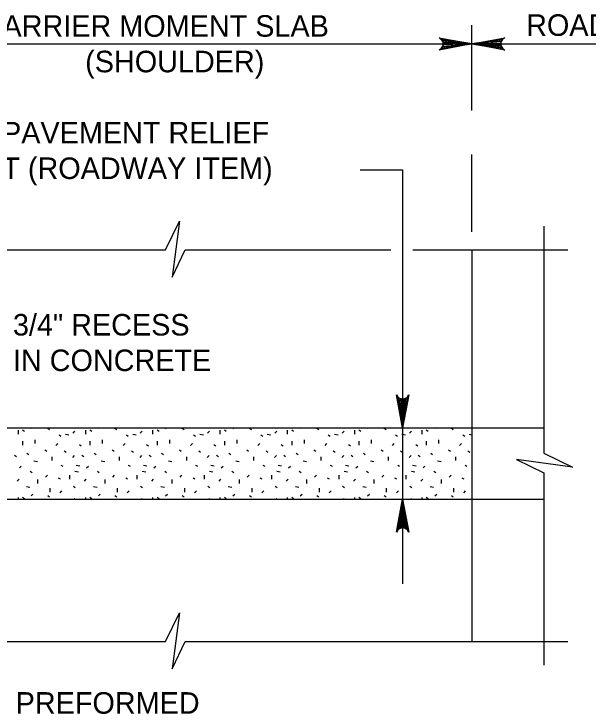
# Model space of a CAD drawing. Extents: x 638167 to 640248, y 296544 to 298920.
# Drawn here: x 640003.4 to 640085.5, y 296853.3 to 296953.1 of the extents above; entities that cross this region are included whole.
import ezdxf

# ---------------------------------------------------------------- set-up
doc = ezdxf.new("R2010")
doc.units = 0
doc.layers.add('1', color=7, linetype='Continuous')

msp = doc.modelspace()

# ---------------------------------------------------------------- linework, layer by layer
at = {"layer": '1'}
for p, q in [((640068.761, 296939.399), (640068.761, 296951.547)), ((639941.261, 296948.882), (640107.801, 296948.882)), ((640068.761, 296922.077), (640068.761, 296933.1)), ((640052.814, 296930.906), (640058.871, 296930.906)), ((640058.871, 296930.906), (640058.871, 296871.848)), ((640079.03, 296922.878), (640079.03, 296890.471)), ((639980.08, 296919.492), (640025.054, 296919.492)), ((640027.825, 296919.492), (640057.194, 296919.492)), ((640060.344, 296919.492), (640082.417, 296919.492)), ((640068.761, 296919.492), (640068.761, 296863.612)), ((639987.481, 296894.092), (640079.03, 296894.092)), ((640004.053, 296893.218), (640004.053, 296893.76)), ((640004.912, 296893.58), (640004.641, 296893.76)), ((640005.861, 296893.987), (640005.966, 296894.092)), ((640008.499, 296893.806), (640008.228, 296893.986)), ((640013.653, 296893.218), (640013.653, 296893.76)), ((640014.512, 296893.58), (640014.241, 296893.76)), ((640015.461, 296893.987), (640015.566, 296894.092)), ((640018.099, 296893.806), (640017.828, 296893.986)), ((640023.253, 296893.218), (640023.253, 296893.76)), ((640024.112, 296893.58), (640023.841, 296893.76)), ((640025.061, 296893.987), (640025.166, 296894.092)), ((640027.699, 296893.806), (640027.428, 296893.986)), ((640032.853, 296893.218), (640032.853, 296893.76)), ((640033.712, 296893.58), (640033.441, 296893.76)), ((640034.661, 296893.987), (640034.766, 296894.092)), ((640037.299, 296893.806), (640037.028, 296893.986)), ((640042.453, 296893.218), (640042.453, 296893.76)), ((640043.312, 296893.58), (640043.041, 296893.76)), ((640044.261, 296893.987), (640044.366, 296894.092)), ((640046.899, 296893.806), (640046.628, 296893.986)), ((640052.053, 296893.218), (640052.053, 296893.76)), ((640052.912, 296893.58), (640052.641, 296893.76)), ((640053.861, 296893.987), (640053.966, 296894.092)), ((640056.499, 296893.806), (640056.228, 296893.986)), ((640061.653, 296893.218), (640061.653, 296893.76)), ((640062.512, 296893.58), (640062.241, 296893.76)), ((640063.461, 296893.987), (640063.566, 296894.092)), ((640066.099, 296893.806), (640065.828, 296893.986)), ((640010.127, 296892.856), (640009.855, 296893.037)), ((640010.76, 296893.173), (640011.257, 296893.082)), ((640011.845, 296893.354), (640012.116, 296893.625)), ((640019.727, 296892.856), (640019.455, 296893.037)), ((640020.36, 296893.173), (640020.857, 296893.082)), ((640021.445, 296893.354), (640021.716, 296893.625)), ((640029.327, 296892.856), (640029.055, 296893.037)), ((640029.96, 296893.173), (640030.457, 296893.082)), ((640031.045, 296893.354), (640031.316, 296893.625)), ((640038.927, 296892.856), (640038.655, 296893.037)), ((640039.56, 296893.173), (640040.057, 296893.082)), ((640040.645, 296893.354), (640040.916, 296893.625)), ((640048.527, 296892.856), (640048.255, 296893.037)), ((640049.16, 296893.173), (640049.657, 296893.082)), ((640050.245, 296893.354), (640050.516, 296893.625)), ((640058.127, 296892.856), (640057.855, 296893.037)), ((640058.76, 296893.173), (640059.257, 296893.082)), ((640059.845, 296893.354), (640060.116, 296893.625)), ((640067.727, 296892.856), (640067.455, 296893.037)), ((640068.36, 296893.173), (640068.761, 296893.1)), ((640004.686, 296891.636), (640004.686, 296892.178)), ((640006.449, 296891.862), (640006.449, 296892.404)), ((640009.404, 296891.59), (640009.675, 296891.862)), ((640013.02, 296891.5), (640012.749, 296891.681)), ((640014.286, 296891.636), (640014.286, 296892.178)), ((640016.049, 296891.862), (640016.049, 296892.404)), ((640019.004, 296891.59), (640019.275, 296891.862)), ((640022.62, 296891.5), (640022.349, 296891.681)), ((640023.886, 296891.636), (640023.886, 296892.178)), ((640025.649, 296891.862), (640025.649, 296892.404)), ((640028.604, 296891.59), (640028.875, 296891.862)), ((640032.22, 296891.5), (640031.949, 296891.681)), ((640033.486, 296891.636), (640033.486, 296892.178)), ((640035.249, 296891.862), (640035.249, 296892.404)), ((640038.204, 296891.59), (640038.475, 296891.862)), ((640041.82, 296891.5), (640041.549, 296891.681)), ((640043.086, 296891.636), (640043.086, 296892.178)), ((640044.849, 296891.862), (640044.849, 296892.404)), ((640047.804, 296891.59), (640048.075, 296891.862)), ((640051.42, 296891.5), (640051.149, 296891.681)), ((640052.686, 296891.636), (640052.686, 296892.178)), ((640054.449, 296891.862), (640054.449, 296892.404)), ((640057.404, 296891.59), (640057.675, 296891.862)), ((640061.02, 296891.5), (640060.749, 296891.681)), ((640062.286, 296891.636), (640062.286, 296892.178)), ((640064.049, 296891.862), (640064.049, 296892.404)), ((640067.004, 296891.59), (640067.275, 296891.862)), ((640008.093, 296890.732), (640007.821, 296890.912)), ((640010.85, 296890.596), (640010.579, 296890.777)), ((640017.693, 296890.732), (640017.421, 296890.912)), ((640020.45, 296890.596), (640020.179, 296890.777)), ((640027.293, 296890.732), (640027.021, 296890.912)), ((640030.05, 296890.596), (640029.779, 296890.777)), ((640036.893, 296890.732), (640036.621, 296890.912)), ((640039.65, 296890.596), (640039.379, 296890.777)), ((640046.493, 296890.732), (640046.221, 296890.912)), ((640049.25, 296890.596), (640048.979, 296890.777)), ((640056.093, 296890.732), (640055.821, 296890.912)), ((640058.85, 296890.596), (640058.579, 296890.777)), ((640065.693, 296890.732), (640065.421, 296890.912)), ((640068.45, 296890.596), (640068.179, 296890.777)), ((640003.782, 296889.963), (640003.51, 296890.144)), ((640005.545, 296890.234), (640005.273, 296890.415)), ((640008.861, 296889.421), (640008.861, 296889.963)), ((640011.8, 296889.873), (640012.071, 296890.144)), ((640013.382, 296889.963), (640013.11, 296890.144)), ((640015.145, 296890.234), (640014.873, 296890.415)), ((640018.461, 296889.421), (640018.461, 296889.963)), ((640021.4, 296889.873), (640021.671, 296890.144)), ((640022.982, 296889.963), (640022.71, 296890.144)), ((640024.745, 296890.234), (640024.473, 296890.415)), ((640028.061, 296889.421), (640028.061, 296889.963)), ((640031, 296889.873), (640031.271, 296890.144)), ((640032.582, 296889.963), (640032.31, 296890.144)), ((640034.345, 296890.234), (640034.073, 296890.415)), ((640037.661, 296889.421), (640037.661, 296889.963)), ((640040.6, 296889.873), (640040.871, 296890.144)), ((640042.182, 296889.963), (640041.91, 296890.144)), ((640043.945, 296890.234), (640043.673, 296890.415)), ((640047.261, 296889.421), (640047.261, 296889.963)), ((640050.2, 296889.873), (640050.471, 296890.144)), ((640051.782, 296889.963), (640051.51, 296890.144)), ((640053.545, 296890.234), (640053.273, 296890.415)), ((640056.861, 296889.421), (640056.861, 296889.963)), ((640059.8, 296889.873), (640060.071, 296890.144)), ((640061.382, 296889.963), (640061.11, 296890.144)), ((640063.145, 296890.234), (640062.873, 296890.415)), ((640066.461, 296889.421), (640066.461, 296889.963)), ((640006.268, 296889.375), (640006.765, 296889.285)), ((640010.443, 296888.562), (640010.172, 296888.742)), ((640012.297, 296888.788), (640012.794, 296888.697)), ((640015.868, 296889.375), (640016.365, 296889.285)), ((640020.043, 296888.562), (640019.772, 296888.742)), ((640021.897, 296888.788), (640022.394, 296888.697)), ((640025.468, 296889.375), (640025.965, 296889.285)), ((640029.643, 296888.562), (640029.372, 296888.742)), ((640031.497, 296888.788), (640031.994, 296888.697)), ((640035.068, 296889.375), (640035.565, 296889.285)), ((640039.243, 296888.562), (640038.972, 296888.742)), ((640041.097, 296888.788), (640041.594, 296888.697)), ((640044.668, 296889.375), (640045.165, 296889.285)), ((640048.843, 296888.562), (640048.572, 296888.742)), ((640050.697, 296888.788), (640051.194, 296888.697)), ((640054.268, 296889.375), (640054.765, 296889.285)), ((640058.443, 296888.562), (640058.172, 296888.742)), ((640060.297, 296888.788), (640060.794, 296888.697)), ((640063.868, 296889.375), (640064.365, 296889.285)), ((640068.043, 296888.562), (640067.772, 296888.742)), ((640004.189, 296888.381), (640004.46, 296888.652)), ((640005.997, 296887.703), (640005.725, 296887.884)), ((640012.116, 296887.929), (640012.613, 296887.838)), ((640013.789, 296888.381), (640014.06, 296888.652)), ((640015.597, 296887.703), (640015.325, 296887.884)), ((640021.716, 296887.929), (640022.213, 296887.838)), ((640023.389, 296888.381), (640023.66, 296888.652)), ((640025.197, 296887.703), (640024.925, 296887.884)), ((640031.316, 296887.929), (640031.813, 296887.838)), ((640032.989, 296888.381), (640033.26, 296888.652)), ((640034.797, 296887.703), (640034.525, 296887.884)), ((640040.916, 296887.929), (640041.413, 296887.838)), ((640042.589, 296888.381), (640042.86, 296888.652)), ((640044.397, 296887.703), (640044.125, 296887.884)), ((640050.516, 296887.929), (640051.013, 296887.838)), ((640052.189, 296888.381), (640052.46, 296888.652)), ((640053.997, 296887.703), (640053.725, 296887.884)), ((640060.116, 296887.929), (640060.613, 296887.838)), ((640061.789, 296888.381), (640062.06, 296888.652)), ((640063.597, 296887.703), (640063.325, 296887.884)), ((640079.03, 296887.7), (640079.03, 296860.225)), ((640003.872, 296886.482), (640004.143, 296886.753)), ((640006.811, 296886.166), (640006.811, 296886.708)), ((640007.912, 296887.07), (640008.183, 296887.341)), ((640010.037, 296886.753), (640009.765, 296886.934)), ((640011.393, 296886.799), (640011.393, 296887.341)), ((640013.472, 296886.482), (640013.743, 296886.753)), ((640016.411, 296886.166), (640016.411, 296886.708)), ((640017.512, 296887.07), (640017.783, 296887.341)), ((640019.637, 296886.753), (640019.365, 296886.934)), ((640020.993, 296886.799), (640020.993, 296887.341)), ((640023.072, 296886.482), (640023.343, 296886.753)), ((640026.011, 296886.166), (640026.011, 296886.708)), ((640027.112, 296887.07), (640027.383, 296887.341)), ((640029.237, 296886.753), (640028.965, 296886.934)), ((640030.593, 296886.799), (640030.593, 296887.341)), ((640032.672, 296886.482), (640032.943, 296886.753)), ((640035.611, 296886.166), (640035.611, 296886.708)), ((640036.712, 296887.07), (640036.983, 296887.341)), ((640038.837, 296886.753), (640038.565, 296886.934)), ((640040.193, 296886.799), (640040.193, 296887.341)), ((640042.272, 296886.482), (640042.543, 296886.753)), ((640045.211, 296886.166), (640045.211, 296886.708)), ((640046.312, 296887.07), (640046.583, 296887.341)), ((640048.437, 296886.753), (640048.165, 296886.934)), ((640049.793, 296886.799), (640049.793, 296887.341)), ((640051.872, 296886.482), (640052.143, 296886.753)), ((640054.811, 296886.166), (640054.811, 296886.708)), ((640055.912, 296887.07), (640056.183, 296887.341)), ((640058.037, 296886.753), (640057.765, 296886.934)), ((640059.393, 296886.799), (640059.393, 296887.341)), ((640061.472, 296886.482), (640061.743, 296886.753)), ((640064.411, 296886.166), (640064.411, 296886.708)), ((640065.512, 296887.07), (640065.783, 296887.341)), ((640067.637, 296886.753), (640067.365, 296886.934)), ((640005.183, 296885.743), (640005.681, 296885.652)), ((640012.161, 296885.562), (640011.89, 296885.743)), ((640014.783, 296885.743), (640015.281, 296885.652)), ((640021.761, 296885.562), (640021.49, 296885.743)), ((640024.383, 296885.743), (640024.881, 296885.652)), ((640031.361, 296885.562), (640031.09, 296885.743)), ((640033.983, 296885.743), (640034.481, 296885.652)), ((640040.961, 296885.562), (640040.69, 296885.743)), ((640043.583, 296885.743), (640044.081, 296885.652)), ((640050.561, 296885.562), (640050.29, 296885.743)), ((640053.183, 296885.743), (640053.681, 296885.652)), ((640060.161, 296885.562), (640059.89, 296885.743)), ((640062.783, 296885.743), (640063.281, 296885.652)), ((640008.59, 296884.929), (640008.59, 296885.471)), ((640009.991, 296884.838), (640010.263, 296885.11)), ((640018.19, 296884.929), (640018.19, 296885.471)), ((640019.591, 296884.838), (640019.863, 296885.11)), ((640027.79, 296884.929), (640027.79, 296885.471)), ((640029.191, 296884.838), (640029.463, 296885.11)), ((640037.39, 296884.929), (640037.39, 296885.471)), ((640038.791, 296884.838), (640039.063, 296885.11)), ((640046.99, 296884.929), (640046.99, 296885.471)), ((640048.391, 296884.838), (640048.663, 296885.11)), ((640056.59, 296884.929), (640056.59, 296885.471)), ((640057.991, 296884.838), (640058.263, 296885.11)), ((640066.19, 296884.929), (640066.19, 296885.471)), ((640067.591, 296884.838), (640067.863, 296885.11)), ((639987.481, 296883.932), (640079.03, 296883.932)), ((640004.053, 296883.932), (640004.053, 296884.16)), ((640004.912, 296883.98), (640004.641, 296884.16)), ((640005.861, 296884.387), (640006.133, 296884.658)), ((640008.499, 296884.206), (640008.228, 296884.386)), ((640012.023, 296883.932), (640012.116, 296884.025)), ((640013.653, 296883.932), (640013.653, 296884.16)), ((640014.512, 296883.98), (640014.241, 296884.16)), ((640015.461, 296884.387), (640015.733, 296884.658)), ((640018.099, 296884.206), (640017.828, 296884.386)), ((640021.623, 296883.932), (640021.716, 296884.025)), ((640023.253, 296883.932), (640023.253, 296884.16)), ((640024.112, 296883.98), (640023.841, 296884.16)), ((640025.061, 296884.387), (640025.333, 296884.658)), ((640027.699, 296884.206), (640027.428, 296884.386)), ((640031.223, 296883.932), (640031.316, 296884.025)), ((640032.853, 296883.932), (640032.853, 296884.16)), ((640033.712, 296883.98), (640033.441, 296884.16)), ((640034.661, 296884.387), (640034.933, 296884.658)), ((640037.299, 296884.206), (640037.028, 296884.386)), ((640040.823, 296883.932), (640040.916, 296884.025)), ((640042.453, 296883.932), (640042.453, 296884.16)), ((640043.312, 296883.98), (640043.041, 296884.16)), ((640044.261, 296884.387), (640044.533, 296884.658)), ((640046.899, 296884.206), (640046.628, 296884.386)), ((640050.423, 296883.932), (640050.516, 296884.025)), ((640052.053, 296883.932), (640052.053, 296884.16)), ((640052.912, 296883.98), (640052.641, 296884.16)), ((640053.861, 296884.387), (640054.133, 296884.658)), ((640056.499, 296884.206), (640056.228, 296884.386)), ((640060.023, 296883.932), (640060.116, 296884.025)), ((640061.653, 296883.932), (640061.653, 296884.16)), ((640062.512, 296883.98), (640062.241, 296884.16)), ((640063.461, 296884.387), (640063.733, 296884.658)), ((640066.099, 296884.206), (640065.828, 296884.386)), ((639980.08, 296863.612), (640025.054, 296863.612)), ((640027.825, 296863.612), (640082.417, 296863.612))]:
    msp.add_line(p, q, dxfattribs=at)
for points in [[(640068.761, 296948.882), (640064.063, 296948.001), (640064.244, 296948.127), (640064.425, 296948.252), (640064.519, 296948.41), (640064.612, 296948.567), (640064.639, 296948.725), (640064.666, 296948.882), (640064.639, 296949.04), (640064.612, 296949.197), (640064.519, 296949.355), (640064.425, 296949.512), (640064.244, 296949.638), (640064.063, 296949.763), (640068.761, 296948.882), (640064.244, 296949.638), (640064.425, 296949.512), (640068.761, 296948.882), (640064.519, 296949.355), (640064.612, 296949.197), (640068.761, 296948.882), (640064.639, 296949.04), (640064.666, 296948.882), (640068.761, 296948.882), (640064.639, 296948.725), (640064.612, 296948.567), (640068.761, 296948.882), (640064.519, 296948.41), (640064.425, 296948.252), (640068.761, 296948.882), (640064.244, 296948.127)], [(640068.761, 296948.882), (640073.459, 296949.763), (640073.278, 296949.638), (640073.097, 296949.512), (640073.003, 296949.355), (640072.91, 296949.197), (640072.883, 296949.04), (640072.856, 296948.882), (640072.883, 296948.725), (640072.91, 296948.567), (640073.003, 296948.41), (640073.097, 296948.252), (640073.278, 296948.127), (640073.459, 296948.001), (640068.761, 296948.882), (640073.278, 296948.127), (640073.097, 296948.252), (640068.761, 296948.882), (640073.003, 296948.41), (640072.91, 296948.567), (640068.761, 296948.882), (640072.883, 296948.725), (640072.856, 296948.882), (640068.761, 296948.882), (640072.883, 296949.04), (640072.91, 296949.197), (640068.761, 296948.882), (640073.003, 296949.355), (640073.097, 296949.512), (640068.761, 296948.882), (640073.278, 296949.638)], [(640025.054, 296919.492), (640027.053, 296923.575), (640025.966, 296915.583), (640027.825, 296919.492)], [(640058.871, 296894.092), (640057.991, 296898.789), (640058.116, 296898.608), (640058.241, 296898.427), (640058.399, 296898.334), (640058.556, 296898.241), (640058.714, 296898.214), (640058.871, 296898.187), (640059.029, 296898.214), (640059.186, 296898.241), (640059.344, 296898.334), (640059.501, 296898.427), (640059.627, 296898.608), (640059.752, 296898.789), (640058.871, 296894.092), (640059.627, 296898.608), (640059.501, 296898.427), (640058.871, 296894.092), (640059.344, 296898.334), (640059.186, 296898.241), (640058.871, 296894.092), (640059.029, 296898.214), (640058.871, 296898.187), (640058.871, 296894.092), (640058.714, 296898.214), (640058.556, 296898.241), (640058.871, 296894.092), (640058.399, 296898.334), (640058.241, 296898.427), (640058.871, 296894.092), (640058.116, 296898.608)], [(640079.03, 296890.471), (640083.114, 296888.472), (640075.122, 296889.559), (640079.03, 296887.7)], [(640058.871, 296883.932), (640059.752, 296879.234), (640059.627, 296879.415), (640059.501, 296879.596), (640059.344, 296879.689), (640059.186, 296879.783), (640059.029, 296879.81), (640058.871, 296879.837), (640058.714, 296879.81), (640058.556, 296879.783), (640058.399, 296879.689), (640058.241, 296879.596), (640058.116, 296879.415), (640057.991, 296879.234), (640058.871, 296883.932), (640058.116, 296879.415), (640058.241, 296879.596), (640058.871, 296883.932), (640058.399, 296879.689), (640058.556, 296879.783), (640058.871, 296883.932), (640058.714, 296879.81), (640058.871, 296879.837), (640058.871, 296883.932), (640059.029, 296879.81), (640059.186, 296879.783), (640058.871, 296883.932), (640059.344, 296879.689), (640059.501, 296879.596), (640058.871, 296883.932), (640059.627, 296879.415)], [(640025.054, 296863.612), (640027.053, 296867.695), (640025.966, 296859.703), (640027.825, 296863.612)]]:
    msp.add_lwpolyline(points, dxfattribs=at)

# ---------------------------------------------------------------- texts
for s, p in [('BARRIER MOMENT SLAB', (639999.041, 296949.899)), ('ROADWAY', (640076.492, 296950.026)), ('(SHOULDER)', (640013.579, 296944.827)), ('1\'-0" PAVEMENT RELIEF', (639992.399, 296934.673)), ('JOINT (ROADWAY ITEM)', (639992.399, 296929.601)), ('3/4" RECESS', (640003.27, 296907.269)), ('IN CONCRETE', (640003.27, 296902.197)), ('PREFORMED', (640003.659, 296853.314))]:
    msp.add_text(s, height=3.072, dxfattribs=at).set_placement(p)

doc.saveas('drawing.dxf')
